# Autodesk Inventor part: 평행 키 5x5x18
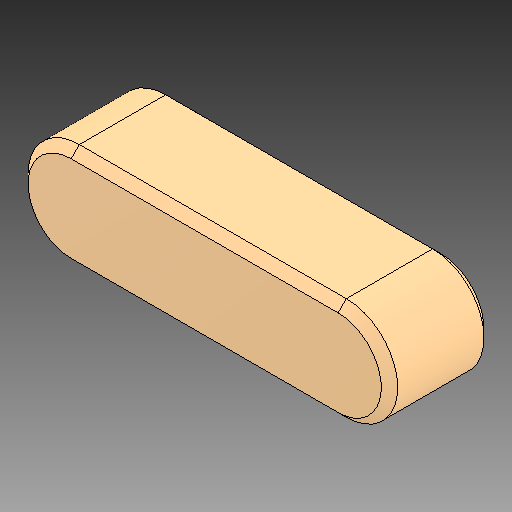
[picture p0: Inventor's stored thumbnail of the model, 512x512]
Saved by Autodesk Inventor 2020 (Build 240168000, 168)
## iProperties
Created: 2025-03
Part Number: 평행 키 5x5x18
Material: 강철, 연강
Description: 키 및 해당 키홈
Document SubType Name: Modeling
Designer: CA01
Density: 7.85 g/cm^3
Appearance: 기본값
Author: jhkim
Sending System: Autodesk Inventor 2025
Preprocessor: ST-DEVELOPER v20
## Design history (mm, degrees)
feature "Solid1"
node "솔리드1"
